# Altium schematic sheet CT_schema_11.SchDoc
size 386 x 278 mm
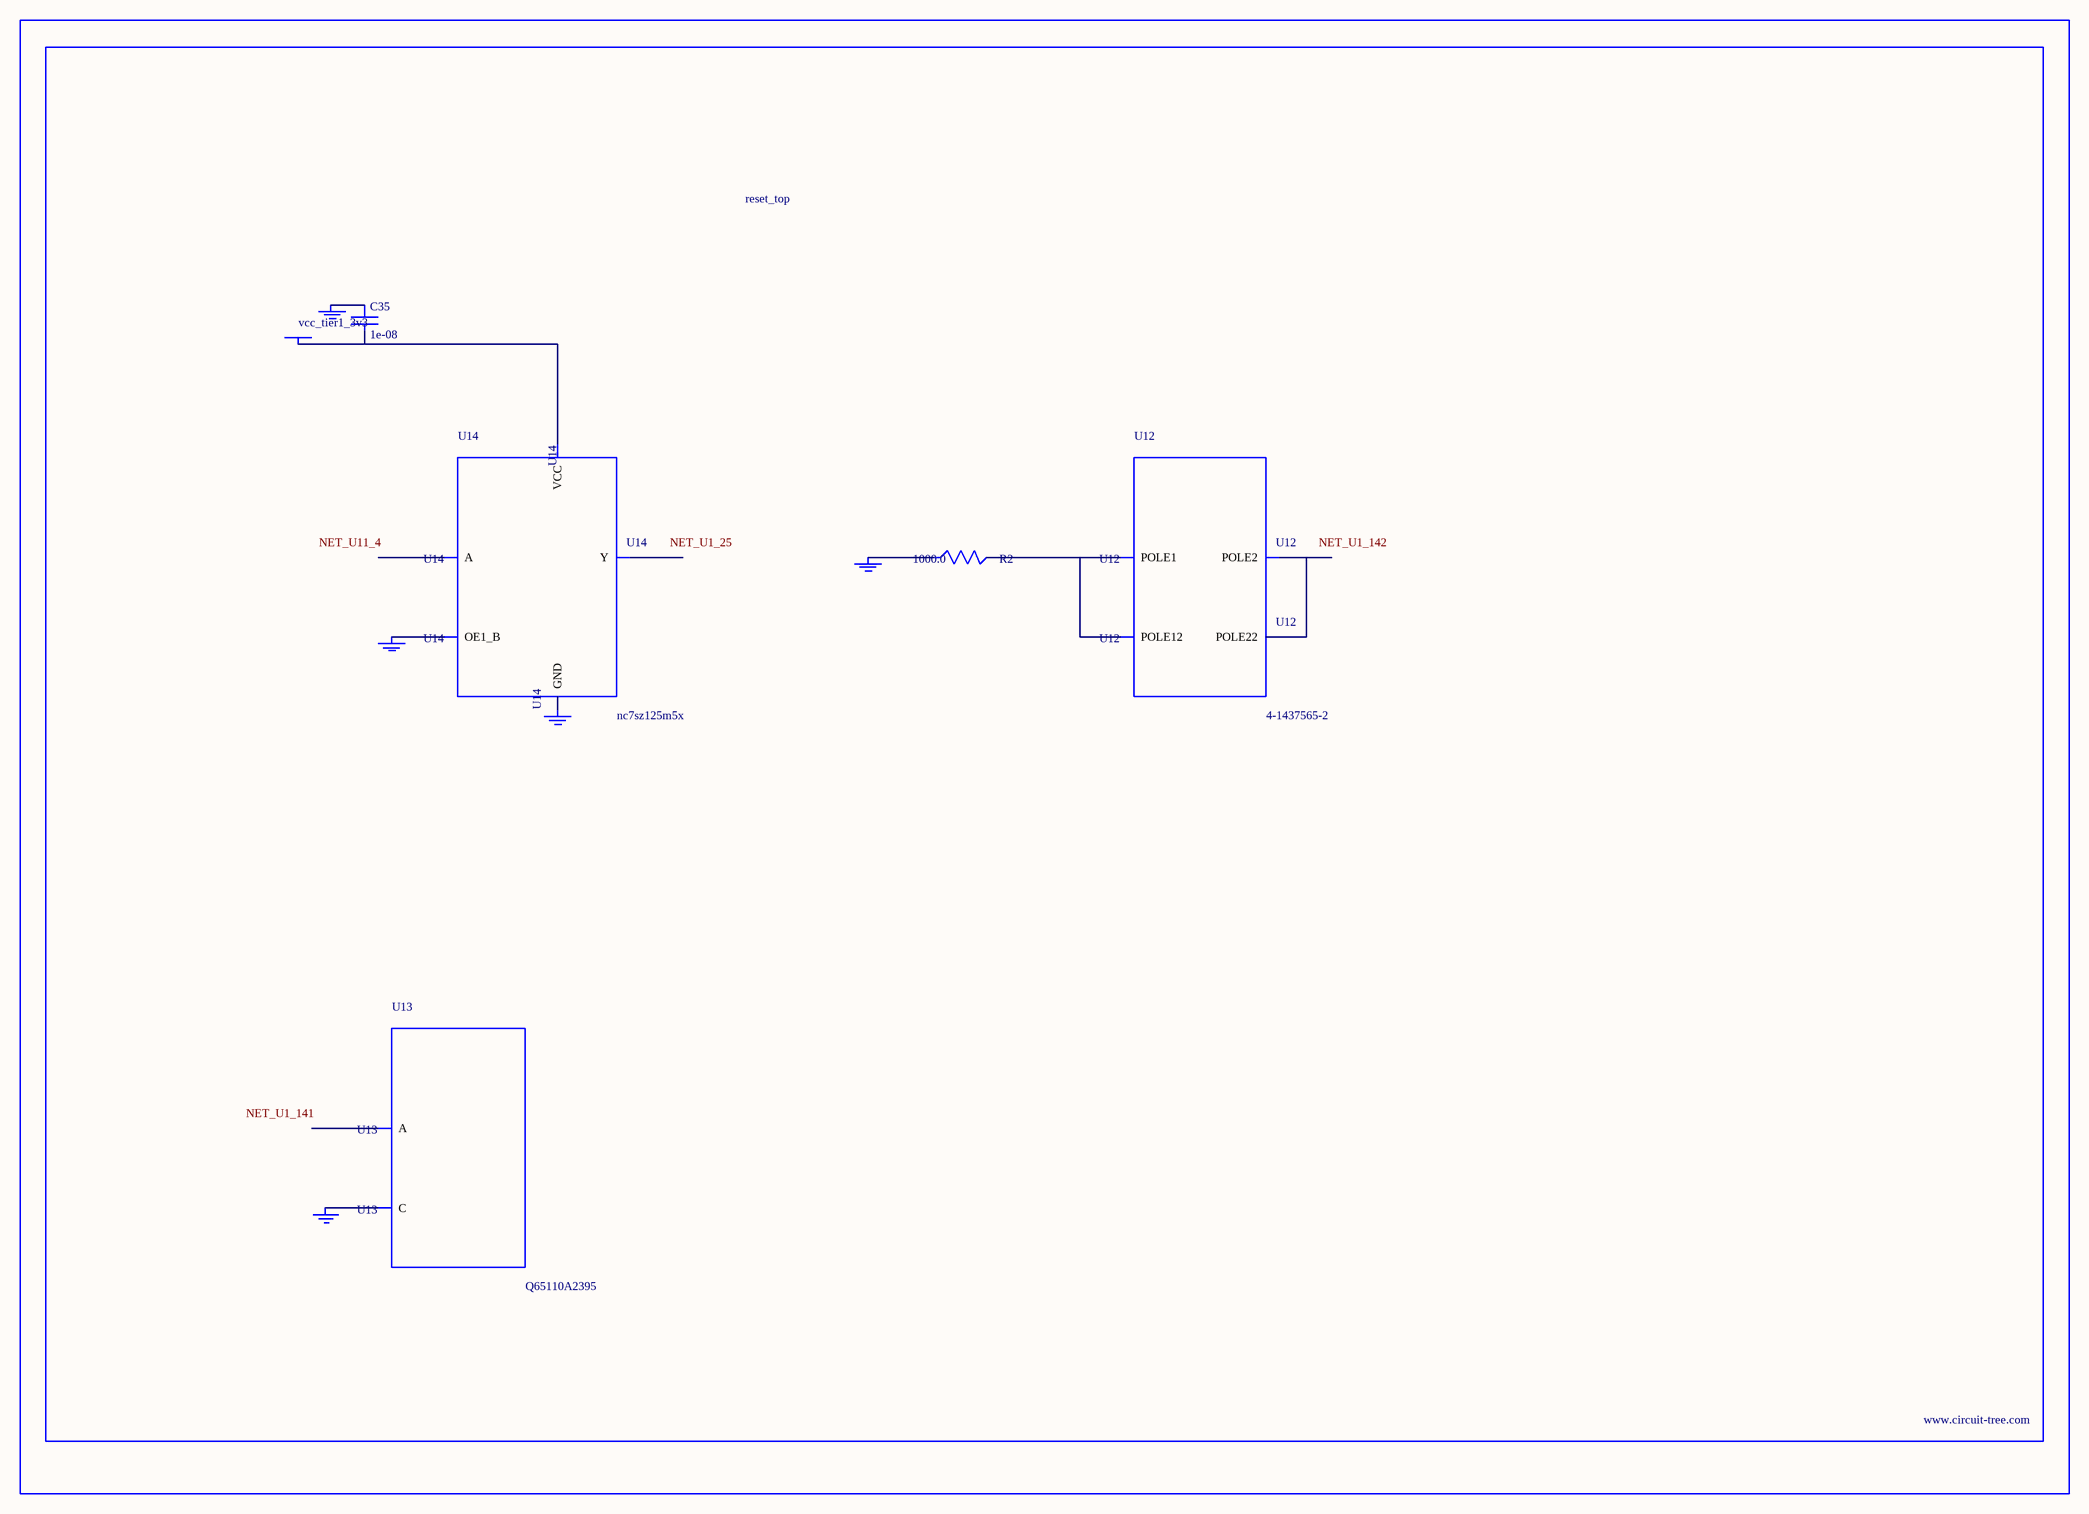
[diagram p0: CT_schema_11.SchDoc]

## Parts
BORDER10  (no value)
C35  1e-08  [C0402]
GND_INSTANCE_10_0  (no value)
GND_INSTANCE_10_1  (no value)
GND_INSTANCE_10_2  (no value)
GND_INSTANCE_10_3  (no value)
GND_INSTANCE_10_4  (no value)
POWER_INSTANCE_10_0  vcc_tier1_3v3
R2  1000.0  [R0603]
U12  4-1437565-2  [SW_4-1437565-2]
U13  Q65110A2395  [LGM67K-G1J2-24-Z]
U14  nc7sz125m5x  [NC7SZ125M5X]

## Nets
NetC35_1: C35.1 GND_INSTANCE_10_2.0(GND)
NetC35_2: C35.2 POWER_INSTANCE_10_0.0(PWR) U14.5(VCC)
NetGND_INSTANCE_10_0_0: GND_INSTANCE_10_0.0(GND) R2.1
NetGND_INSTANCE_10_1_0: GND_INSTANCE_10_1.0(GND) U13.C
NetGND_INSTANCE_10_3_0: GND_INSTANCE_10_3.0(GND) U14.1(OE1_B)
NetGND_INSTANCE_10_4_0: GND_INSTANCE_10_4.0(GND) U14.3(GND)
NetR2_2: R2.2 U12.1(POLE1) U12.2(POLE12)
NetU12_3: U12.3(POLE2) U12.4(POLE22)

Not connected (* = marked no-connect by the designer): U13 A; U14 2(A) 4(Y)

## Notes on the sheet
- Labels drawn without touching a wire or pin: NET_U1_25, NET_U1_141, NET_U1_142, NET_U11_4

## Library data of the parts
BORDER10 = BORDER_PAGE10
C35 = C0402C103K3RAC
GND_INSTANCE_10_0-GND_INSTANCE_10_4 = GND
POWER_INSTANCE_10_0 = PWR
R2 = RC0603JR-071KL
